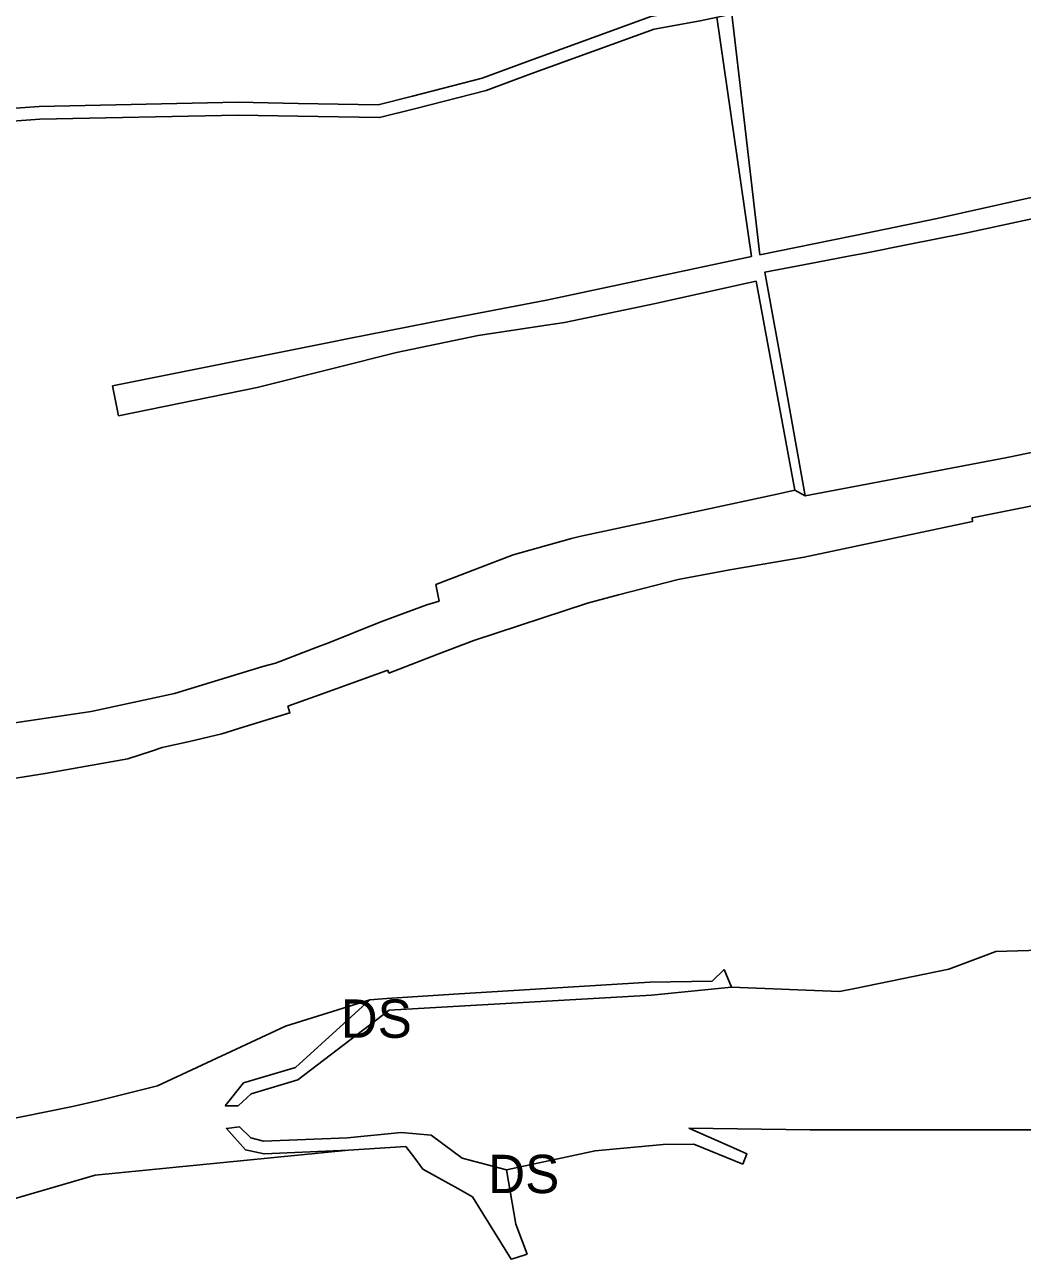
# Model space of a CAD drawing. Extents: x -477304 to -465641, y -1159113 to -1149285.
# Drawn here: x -473987.6 to -473753.4, y -1154180.7 to -1153890.9 of the extents above; entities that cross this region are included whole.
import ezdxf

# ---------------------------------------------------------------- set-up
doc = ezdxf.new("R2010")
doc.units = 0
for name, color, linetype in [('14', 7, 'Continuous'), ('22', 7, 'Continuous'), ('34', 7, 'Continuous'), ('35', 7, 'Continuous')]:
    doc.layers.add(name, color=color, linetype=linetype)

msp = doc.modelspace()

# ---------------------------------------------------------------- linework, layer by layer
at = {"layer": '14'}
for p, q in [((-473937.55, -1153909.09), (-473984.24, -1153910.04)), ((-473984.24, -1153910.04), (-474084.13, -1153917.32)), ((-473984.1, -1153913.03), (-473937.55, -1153912.09))]:
    msp.add_line(p, q, dxfattribs=at)
for points in [[(-473654.01, -1153964.1), (-473662.88, -1153952.1), (-473679.76, -1153933), (-473698.46, -1153911.82), (-473708.81, -1153900.98), (-473728.75, -1153888.56), (-473740.8, -1153882.07), (-473760.24, -1153880.49), (-473763.95, -1153880.49), (-473785.03, -1153879.61), (-473790.98, -1153878.15), (-473804.82, -1153881.15), (-473821.95, -1153885.37), (-473825.56, -1153886.13), (-473829.66, -1153887.01), (-473840.62, -1153888.98), (-473869.82, -1153899.62), (-473880.2, -1153903.41), (-473896.57, -1153907.65), (-473904.64, -1153909.68), (-473923.44, -1153909.34), (-473937.55, -1153909.09)], [(-473937.55, -1153912.09), (-473923.49, -1153912.34), (-473904.3, -1153912.69), (-473895.83, -1153910.56), (-473879.31, -1153906.28), (-473868.79, -1153902.44), (-473839.84, -1153891.89), (-473829.08, -1153889.95), (-473824.94, -1153889.06), (-473821.28, -1153888.3), (-473804.14, -1153884.07), (-473791.02, -1153881.23), (-473785.45, -1153882.59), (-473764.01, -1153883.49), (-473760.36, -1153883.49), (-473741.67, -1153885.01), (-473730.26, -1153891.16), (-473710.72, -1153903.33), (-473700.67, -1153913.85), (-473682.01, -1153934.99), (-473665.21, -1153953.99), (-473657.19, -1153964.84)], [(-474218.68, -1153941.87), (-474161.53, -1153930.15), (-474122.04, -1153922.31), (-474080.14, -1153923.66), (-474080.68, -1153920.08), (-473984.1, -1153913.03)]]:
    msp.add_lwpolyline(points, dxfattribs=at)
at = {"layer": '22'}
for p, q in [((-473759.66, -1154108.44), (-473762.51, -1154109.56)), ((-473749.31, -1154108.12), (-473759.66, -1154108.44)), ((-473762.51, -1154109.56), (-473770.68, -1154112.63)), ((-473770.68, -1154112.63), (-473792.72, -1154117.16)), ((-473821.72, -1154116.87), (-473840.5, -1154118.69)), ((-473796.31, -1154117.9), (-473821.72, -1154116.87)), ((-473792.72, -1154117.16), (-473796.31, -1154117.9)), ((-473906.58, -1154119.78), (-473926.4, -1154125.97)), ((-473924.04, -1154135.71), (-473906.58, -1154119.78)), ((-473840.5, -1154118.69), (-473902.04, -1154122.24)), ((-473902.04, -1154122.24), (-473923.47, -1154138.63)), ((-473936.25, -1154139.33), (-473924.04, -1154135.71)), ((-473940.58, -1154144.71), (-473936.25, -1154139.33)), ((-473970.27, -1154143.45), (-473976.41, -1154144.89)), ((-473976.41, -1154144.89), (-473999.54, -1154149.56)), ((-473937.54, -1154144.73), (-473940.58, -1154144.71)), ((-473931.55, -1154153.03), (-473911.82, -1154152.18)), ((-473911.82, -1154152.18), (-473899.28, -1154150.96)), ((-473820.48, -1154154.9), (-473831.68, -1154149.93)), ((-473781.51, -1154150.34), (-473737.23, -1154150.39)), ((-473971.11, -1154160.95), (-473911.65, -1154155.13)), ((-473911.65, -1154155.13), (-473931.45, -1154155.98)), ((-473837.72, -1154153.77), (-473830.53, -1154153.71)), ((-473830.53, -1154153.71), (-473819.04, -1154158.38)), ((-474015.16, -1154173.81), (-473971.11, -1154160.95))]:
    msp.add_line(p, q, dxfattribs=at)
for points in [[(-473926.4, -1154125.97), (-473956.47, -1154139.98), (-473970.27, -1154143.45)], [(-473923.47, -1154138.63), (-473934.49, -1154141.85), (-473937.54, -1154144.73)], [(-473931.45, -1154155.98), (-473935.81, -1154155.04), (-473940.27, -1154150.02), (-473937.24, -1154149.65), (-473934.58, -1154152.23), (-473931.55, -1154153.03)], [(-473899.28, -1154150.96), (-473892.23, -1154151.6), (-473884.93, -1154157.03)], [(-473831.68, -1154149.93), (-473803.24, -1154150.32), (-473781.51, -1154150.34)], [(-473884.93, -1154157.03), (-473874.52, -1154159.76), (-473853.73, -1154155.26), (-473837.72, -1154153.77)], [(-473819.04, -1154158.38), (-473818.08, -1154155.96), (-473820.48, -1154154.9)]]:
    msp.add_lwpolyline(points, dxfattribs=at)
at = {"layer": '34'}
for p, q in [((-473818.31, -1153916.59), (-473821.6, -1153888.36)), ((-473825.13, -1153889.11), (-473816.99, -1153945.28)), ((-473815.01, -1153944.88), (-473818.31, -1153916.59)), ((-473750.61, -1153931.25), (-473767.45, -1153935.02)), ((-473767.45, -1153935.02), (-473773.42, -1153936.36)), ((-473767.16, -1153939.87), (-473744.27, -1153935)), ((-473773.42, -1153936.36), (-473792.76, -1153940.37)), ((-473792.76, -1153940.37), (-473798.13, -1153941.47)), ((-473780.23, -1153942.47), (-473767.16, -1153939.87)), ((-473798.13, -1153941.47), (-473815.01, -1153944.88)), ((-473790.32, -1153944.47), (-473780.23, -1153942.47)), ((-473816.99, -1153945.28), (-473865.09, -1153955.58)), ((-473839.53, -1153956.34), (-473819.47, -1153951.9)), ((-473819.47, -1153951.9), (-473815.91, -1153951.11)), ((-473815.91, -1153951.11), (-473806.81, -1154000.19)), ((-473865.09, -1153955.58), (-473888.08, -1153959.95)), ((-473860.93, -1153960.79), (-473839.53, -1153956.34)), ((-473888.08, -1153959.95), (-473911.94, -1153964.61)), ((-473865.16, -1153961.42), (-473860.93, -1153960.79)), ((-473900.35, -1153967.83), (-473881.2, -1153963.82)), ((-473881.2, -1153963.82), (-473865.16, -1153961.42)), ((-473915.77, -1153965.38), (-473932.94, -1153968.82)), ((-473911.94, -1153964.61), (-473915.77, -1153965.38)), ((-473932.94, -1153968.82), (-473967.04, -1153975.65)), ((-473914.63, -1153971.41), (-473900.35, -1153967.83)), ((-473933.06, -1153976.04), (-473914.63, -1153971.41)), ((-473967.04, -1153975.65), (-473965.58, -1153982.7)), ((-473965.58, -1153982.7), (-473933.06, -1153976.04)), ((-473808.63, -1153977.84), (-473808.96, -1153976.03)), ((-473804.37, -1154001.46), (-473808.63, -1153977.84)), ((-473806.81, -1154000.19), (-473804.37, -1154001.46))]:
    msp.add_line(p, q, dxfattribs=at)
for points in [[(-473808.96, -1153976.03), (-473813.84, -1153948.94), (-473801.46, -1153946.59)], [(-473801.46, -1153946.59), (-473793.85, -1153945.14), (-473790.32, -1153944.47)]]:
    msp.add_lwpolyline(points, dxfattribs=at)
at = {"layer": '35'}
for p, q in [((-473733.09, -1153987.61), (-473756.2, -1153992.3)), ((-473757.38, -1153992.53), (-473779.54, -1153996.81)), ((-473756.2, -1153992.3), (-473757.38, -1153992.53)), ((-473779.54, -1153996.81), (-473804.37, -1154001.46)), ((-473810.98, -1154001.08), (-473830.99, -1154005.36)), ((-473806.81, -1154000.19), (-473810.98, -1154001.08)), ((-473804.37, -1154001.46), (-473806.81, -1154000.19)), ((-473830.99, -1154005.36), (-473857.34, -1154011)), ((-473804.65, -1154015.86), (-473765.08, -1154007.48)), ((-473859.26, -1154011.54), (-473872.94, -1154015.36)), ((-473857.34, -1154011), (-473859.26, -1154011.54)), ((-473872.94, -1154015.36), (-473891.08, -1154022.3)), ((-473891.08, -1154022.3), (-473890.32, -1154026.23)), ((-473855.46, -1154026.66), (-473848.18, -1154024.75)), ((-473893.25, -1154027.1), (-473896.22, -1154028.19)), ((-473890.32, -1154026.23), (-473893.25, -1154027.1)), ((-473896.22, -1154028.19), (-473904.01, -1154031.07)), ((-473904.01, -1154031.07), (-473916.86, -1154036.22)), ((-473916.86, -1154036.22), (-473918.18, -1154036.73)), ((-473918.18, -1154036.73), (-473928.73, -1154040.78)), ((-473902.11, -1154043.1), (-473890.62, -1154038.64)), ((-473931.76, -1154041.56), (-473952.44, -1154047.9)), ((-473928.73, -1154040.78), (-473931.76, -1154041.56)), ((-473911.68, -1154045.78), (-473902.34, -1154042.42)), ((-473902.34, -1154042.42), (-473902.11, -1154043.1)), ((-473952.44, -1154047.9), (-473972.02, -1154052.11)), ((-473925.89, -1154050.89), (-473914.29, -1154046.72)), ((-473914.29, -1154046.72), (-473911.68, -1154045.78)), ((-473972.02, -1154052.11), (-473991.04, -1154054.95)), ((-473955.38, -1154060.58), (-473948.97, -1154059.18)), ((-473957.84, -1154061.4), (-473955.38, -1154060.58)), ((-473997.59, -1154069.03), (-473982.85, -1154066.69)), ((-473823.4, -1154112.73), (-473826.26, -1154115.41)), ((-473821.72, -1154116.87), (-473823.4, -1154112.73)), ((-473840.87, -1154115.66), (-473886.88, -1154118.51)), ((-473826.26, -1154115.41), (-473840.87, -1154115.66)), ((-473840.5, -1154118.69), (-473821.72, -1154116.87)), ((-473906.58, -1154119.78), (-473924.04, -1154135.71)), ((-473902.62, -1154119.48), (-473906.58, -1154119.78)), ((-473886.88, -1154118.51), (-473902.62, -1154119.48)), ((-473902.04, -1154122.24), (-473840.5, -1154118.69)), ((-473923.47, -1154138.63), (-473902.04, -1154122.24)), ((-473924.04, -1154135.71), (-473936.25, -1154139.33)), ((-473936.25, -1154139.33), (-473940.58, -1154144.71)), ((-473940.58, -1154144.71), (-473937.54, -1154144.73)), ((-473884.93, -1154157.03), (-473892.23, -1154151.6)), ((-473911.65, -1154155.13), (-473898.13, -1154154.23)), ((-473874.52, -1154159.76), (-473884.93, -1154157.03)), ((-473894.17, -1154159.57), (-473885.93, -1154164.15)), ((-473872.35, -1154172.49), (-473874.52, -1154159.76)), ((-473885.93, -1154164.15), (-473882.51, -1154166.06)), ((-473869.63, -1154179.5), (-473872.35, -1154172.49))]:
    msp.add_line(p, q, dxfattribs=at)
for points in [[(-473765.08, -1154007.48), (-473765.19, -1154006.67), (-473745.65, -1154002.71)], [(-473848.18, -1154024.75), (-473834.2, -1154021.09), (-473822.04, -1154018.83), (-473804.65, -1154015.86)], [(-473890.62, -1154038.64), (-473882.17, -1154035.47), (-473855.46, -1154026.66)], [(-473948.97, -1154059.18), (-473941.36, -1154057.36), (-473936.13, -1154055.69), (-473925.38, -1154052.45), (-473925.89, -1154050.89)], [(-473982.85, -1154066.69), (-473963.44, -1154063.26), (-473957.84, -1154061.4)], [(-473937.54, -1154144.73), (-473934.49, -1154141.85), (-473923.47, -1154138.63)], [(-473934.58, -1154152.23), (-473937.24, -1154149.65), (-473940.27, -1154150.02), (-473935.81, -1154155.04)], [(-473892.23, -1154151.6), (-473899.28, -1154150.96), (-473911.82, -1154152.18), (-473931.55, -1154153.03), (-473934.58, -1154152.23)], [(-473935.81, -1154155.04), (-473931.45, -1154155.98), (-473911.65, -1154155.13)], [(-473898.13, -1154154.23), (-473896.05, -1154157.03), (-473894.17, -1154159.57)], [(-473882.51, -1154166.06), (-473873.45, -1154180.74), (-473872.29, -1154180.36), (-473869.63, -1154179.5)]]:
    msp.add_lwpolyline(points, dxfattribs=at)

# ---------------------------------------------------------------- texts
for p in [(-473913.46, -1154128.73), (-473878.83, -1154165.2)]:
    msp.add_text('DS', height=9, dxfattribs=at).set_placement(p)

doc.saveas('drawing.dxf')
